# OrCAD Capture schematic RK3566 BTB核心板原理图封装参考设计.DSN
size A3; title: 野火_EBF RK3568 BTB 底板; rev: V1.0; note: BTB Connector; note: https://yehuosm.tmall.com
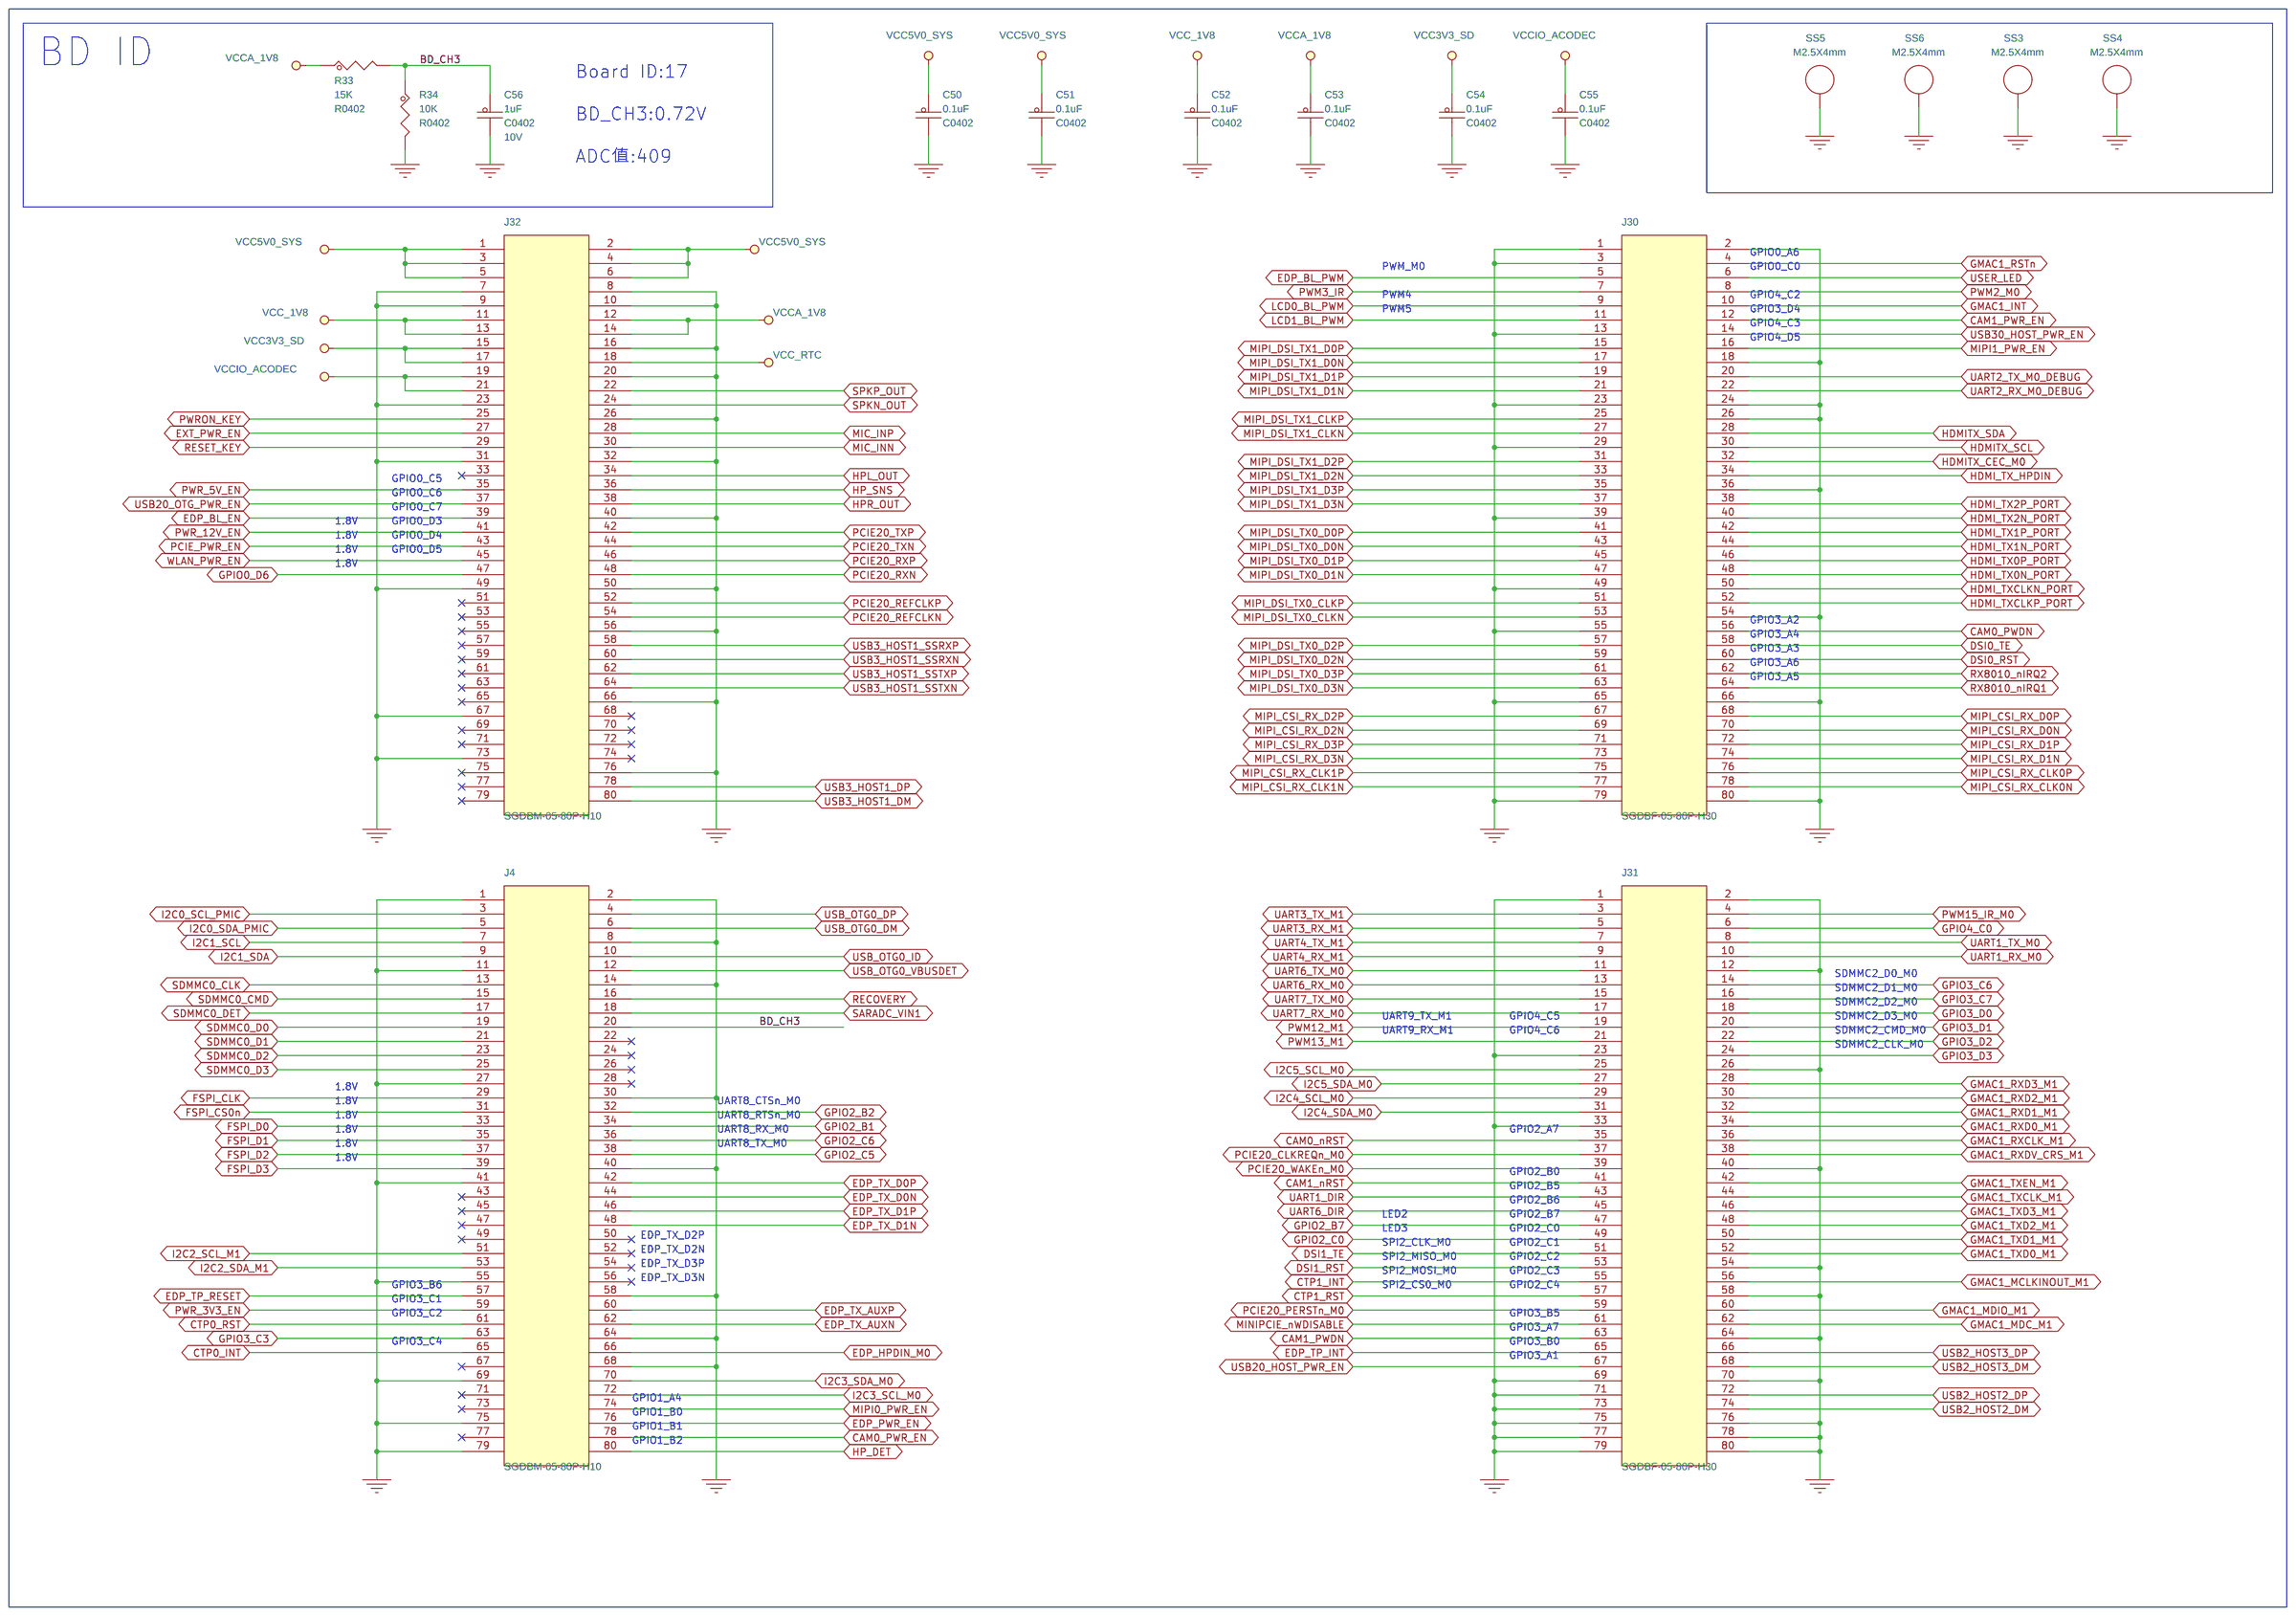
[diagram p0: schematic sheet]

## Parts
C50  0.1uF  [C0402]
C51  0.1uF  [C0402]
C52  0.1uF  [C0402]
C53  0.1uF  [C0402]
C54  0.1uF  [C0402]
C55  0.1uF  [C0402]
C56  1uF  [C0402]
J4  SGDBM-05-80P-H10  [SGDBM-05-80P-H10]
J30  SGDBF-05-80P-H30  [SGDBF-05-80P-H30]
J31  SGDBF-05-80P-H30  [SGDBF-05-80P-H30]
J32  SGDBM-05-80P-H10  [SGDBM-05-80P-H10]
R33  15K  [R0402]
R34  10K  [R0402]
SS3  M2.5X4mm  [SMTSO-M2r5]
SS4  M2.5X4mm  [SMTSO-M2r5]
SS5  M2.5X4mm  [SMTSO-M2r5]
SS6  M2.5X4mm  [SMTSO-M2r5]

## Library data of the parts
C50-C55 = CAP_NP: voltage: 50V; 规格: 贴片电容0.1uF 10% 50V X5R 0402; 规格编号: 0402X104K500NT; 规格书: 风华电容.pdf; 价格: 0.029826; 类别: 贴片电容0402; 品牌: 风华; 生命周期: 量产; 条码: EBF29060118
C56 = CAP_NP: Voltage: 10V; 规格: 贴片电容1uF 10% 10V X5R 0402; 规格编号: 0402X105K100NT; 规格书: 风华电容.pdf; 价格: 0.01191; 类别: 贴片电容0402; 品牌: 风华; 生命周期: 量产; 条码: EBF29060121
J4 J32 = SGDBM-05-80P-H10: 规格: 0.5mm BTB公座2*40P 双槽 立贴式 合高4.0mm; 规格书: 山谷道_双槽板对板公母立贴式0_5mm.pdf; 类别: BTB连接器; 品牌: 山谷道; 生命周期: 量产; 条码: EBFCIS221220164941
J30 J31 = SGDBM-05-80P-H10: 规格: 0.5mm BTB母座2*40P 双槽 立贴式 合高4.0mm; 规格书: 山谷道_双槽板对板公母立贴式0_5mm.pdf; 类别: BTB连接器; 品牌: 山谷道; 生命周期: 量产; 条码: EBFCIS221220165510
R33 = RES: 规格: 贴片电阻15K 1% 1/16W 0402; 规格编号: RI0402L1502FT; 规格书: 合科泰-RI系列电阻.pdf; 类别: 贴片电阻0402; 品牌: 合科泰; 生命周期: 量产; 条码: EBF29070222
R34 = RES: 规格: 贴片电阻10K 1% 1/16W 0402; 规格编号: 0402WGF1002TCE; 规格书: 厚声-无铅厚膜电阻.pdf; 价格: 0.002773; 类别: 贴片电阻0402; 品牌: 厚声; 生命周期: 量产; 条码: EBF29070046
SS3-SS6 = SPACER: 备注: BTB核心板固定铜柱; 规格: SMT贴片螺母M2.5 台阶高度1.4MM 台阶外径：4.5MM 螺柱长度：4MM; 规格编号: SMTSO2540CTJ; 规格书: 雄和远景_SMTSO2530CTJ.pdf; 类别: 贴片螺母; 品牌: 雄和远景; 生命周期: 量产; 条码: EBFCIS230525101139

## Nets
GND: C50.2 C51.2 C52.2 C53.2 C54.2 C55.2 C56.2 J4.1 J4.2 J4.8 J4.11 J4.14 J4.27 J4.30 J4.40 J4.41 J4.55 J4.58 J4.64 J4.68 J4.69 J4.75 J4.79 J30.1 J30.2 J30.3 J30.13 J30.18 J30.23 J30.24 J30.26 J30.29 J30.36 J30.39 J30.49 J30.54 J30.55 J30.65 J30.66 J30.79 J30.80 J31.1 J31.2 J31.12 J31.23 J31.26 J31.33 J31.40 J31.54 J31.58 J31.64 J31.69 J31.70 J31.71 J31.73 J31.75 J31.76 J31.77 J31.78 J31.79 J31.80 J32.7 J32.8 J32.9 J32.10 J32.16 J32.20 J32.23 J32.26 J32.31 J32.32 J32.40 J32.49 J32.50 J32.56 J32.66 J32.67 J32.73 J32.76 R34.2 SS3.1(NC) SS4.1(NC) SS5.1(NC) SS6.1(NC)
VCC3V3_SD: C54.1 J32.15 J32.17
VCC5V0_SYS: C50.1 C51.1 J32.1 J32.2 J32.3 J32.4 J32.5 J32.6
VCC_1V8: C52.1 J32.11 J32.13
VCC_RTC: J32.18
VCCA_1V8: C53.1 J32.12 J32.14 R33.1
VCCIO_ACODEC: C55.1 J32.19 J32.21
BD_CH3: C56.1 J4.20 R33.2 R34.1
CAM0_nRST: J31.35
CAM0_PWDN: J30.56
CAM0_PWR_EN: J4.78
CAM1_nRST: J31.41
CAM1_PWDN: J31.63
CAM1_PWR_EN: J30.12
CTP0_INT: J4.65
CTP0_RST: J4.61
CTP1_INT: J31.55
CTP1_RST: J31.57
DSI0_RST: J30.60
DSI0_TE: J30.58
DSI1_RST: J31.53
DSI1_TE: J31.51
EDP_BL_EN: J32.39
EDP_BL_PWM: J30.5
EDP_HPDIN_M0: J4.66
EDP_PWR_EN: J4.76
EDP_TP_INT: J31.65
EDP_TP_RESET: J4.57
EDP_TX_AUXN: J4.62
EDP_TX_AUXP: J4.60
EDP_TX_D0N: J4.44
EDP_TX_D0P: J4.42
EDP_TX_D1N: J4.48
EDP_TX_D1P: J4.46
EXT_PWR_EN: J32.27
FSPI_CLK: J4.29
FSPI_CS0n: J4.31
FSPI_D0: J4.33
FSPI_D1: J4.35
FSPI_D2: J4.37
FSPI_D3: J4.39
GMAC1_INT: J30.10
GMAC1_MCLKINOUT_M1: J31.56
GMAC1_MDC_M1: J31.62
GMAC1_MDIO_M1: J31.60
GMAC1_RSTn: J30.4
GMAC1_RXCLK_M1: J31.36
GMAC1_RXD0_M1: J31.34
GMAC1_RXD1_M1: J31.32
GMAC1_RXD2_M1: J31.30
GMAC1_RXD3_M1: J31.28
GMAC1_RXDV_CRS_M1: J31.38
GMAC1_TXCLK_M1: J31.44
GMAC1_TXD0_M1: J31.52
GMAC1_TXD1_M1: J31.50
GMAC1_TXD2_M1: J31.48
GMAC1_TXD3_M1: J31.46
GMAC1_TXEN_M1: J31.42
GPIO0_D6: J32.47
GPIO2_B1: J4.34
GPIO2_B2: J4.32
GPIO2_B7: J31.47
GPIO2_C0: J31.49
GPIO2_C5: J4.38
GPIO2_C6: J4.36
GPIO3_C3: J4.63
GPIO3_C6: J31.14
GPIO3_C7: J31.16
GPIO3_D0: J31.18
GPIO3_D1: J31.20
GPIO3_D2: J31.22
GPIO3_D3: J31.24
GPIO4_C0: J31.6
HDMI_TX0N_PORT: J30.48
HDMI_TX0P_PORT: J30.46
HDMI_TX1N_PORT: J30.44
HDMI_TX1P_PORT: J30.42
HDMI_TX2N_PORT: J30.40
HDMI_TX2P_PORT: J30.38
HDMI_TX_HPDIN: J30.34
HDMI_TXCLKN_PORT: J30.50
HDMI_TXCLKP_PORT: J30.52
HDMITX_CEC_M0: J30.32
HDMITX_SCL: J30.30
HDMITX_SDA: J30.28
HP_DET: J4.80
HP_SNS: J32.36
HPL_OUT: J32.34
HPR_OUT: J32.38
I2C0_SCL_PMIC: J4.3
I2C0_SDA_PMIC: J4.5
I2C1_SCL: J4.7
I2C1_SDA: J4.9
I2C2_SCL_M1: J4.51
I2C2_SDA_M1: J4.53
I2C3_SCL_M0: J4.72
I2C3_SDA_M0: J4.70
I2C4_SCL_M0: J31.29
I2C4_SDA_M0: J31.31
I2C5_SCL_M0: J31.25
I2C5_SDA_M0: J31.27
LCD0_BL_PWM: J30.9
LCD1_BL_PWM: J30.11
MIC_INN: J32.30
MIC_INP: J32.28
MINIPCIE_nWDISABLE: J31.61
MIPI0_PWR_EN: J4.74
MIPI1_PWR_EN: J30.16
MIPI_CSI_RX_CLK0N: J30.78
MIPI_CSI_RX_CLK0P: J30.76
MIPI_CSI_RX_CLK1N: J30.77
MIPI_CSI_RX_CLK1P: J30.75
MIPI_CSI_RX_D0N: J30.70
MIPI_CSI_RX_D0P: J30.68
MIPI_CSI_RX_D1N: J30.74
MIPI_CSI_RX_D1P: J30.72
MIPI_CSI_RX_D2N: J30.69
MIPI_CSI_RX_D2P: J30.67
MIPI_CSI_RX_D3N: J30.73
MIPI_CSI_RX_D3P: J30.71
MIPI_DSI_TX0_CLKN: J30.53
MIPI_DSI_TX0_CLKP: J30.51
MIPI_DSI_TX0_D0N: J30.43
MIPI_DSI_TX0_D0P: J30.41
MIPI_DSI_TX0_D1N: J30.47
MIPI_DSI_TX0_D1P: J30.45
MIPI_DSI_TX0_D2N: J30.59
MIPI_DSI_TX0_D2P: J30.57
MIPI_DSI_TX0_D3N: J30.63
MIPI_DSI_TX0_D3P: J30.61
MIPI_DSI_TX1_CLKN: J30.27
MIPI_DSI_TX1_CLKP: J30.25
MIPI_DSI_TX1_D0N: J30.17
MIPI_DSI_TX1_D0P: J30.15
MIPI_DSI_TX1_D1N: J30.21
MIPI_DSI_TX1_D1P: J30.19
MIPI_DSI_TX1_D2N: J30.33
MIPI_DSI_TX1_D2P: J30.31
MIPI_DSI_TX1_D3N: J30.37
MIPI_DSI_TX1_D3P: J30.35
PCIE20_CLKREQn_M0: J31.37
PCIE20_PERSTn_M0: J31.59
PCIE20_REFCLKN: J32.54
PCIE20_REFCLKP: J32.52
PCIE20_RXN: J32.48
PCIE20_RXP: J32.46
PCIE20_TXN: J32.44
PCIE20_TXP: J32.42
PCIE20_WAKEn_M0: J31.39
PCIE_PWR_EN: J32.43
PWM2_M0: J30.8
PWM3_IR: J30.7
PWM12_M1: J31.19
PWM13_M1: J31.21
PWM15_IR_M0: J31.4
PWR_3V3_EN: J4.59
PWR_5V_EN: J32.35
PWR_12V_EN: J32.41
PWRON_KEY: J32.25
RECOVERY: J4.16
RESET_KEY: J32.29
RX8010_nIRQ1: J30.64
RX8010_nIRQ2: J30.62
SARADC_VIN1: J4.18
SDMMC0_CLK: J4.13
SDMMC0_CMD: J4.15
SDMMC0_D0: J4.19
SDMMC0_D1: J4.21
SDMMC0_D2: J4.23
SDMMC0_D3: J4.25
SDMMC0_DET: J4.17
SPKN_OUT: J32.24
SPKP_OUT: J32.22
UART1_DIR: J31.43
UART1_RX_M0: J31.10
UART1_TX_M0: J31.8
UART2_RX_M0_DEBUG: J30.22
UART2_TX_M0_DEBUG: J30.20
UART3_RX_M1: J31.5
UART3_TX_M1: J31.3
UART4_RX_M1: J31.9
UART4_TX_M1: J31.7
UART6_DIR: J31.45
UART6_RX_M0: J31.13
UART6_TX_M0: J31.11
UART7_RX_M0: J31.17
UART7_TX_M0: J31.15
USB2_HOST2_DM: J31.74
USB2_HOST2_DP: J31.72
USB2_HOST3_DM: J31.68
USB2_HOST3_DP: J31.66
USB3_HOST1_DM: J32.80
USB3_HOST1_DP: J32.78
USB3_HOST1_SSRXN: J32.60
USB3_HOST1_SSRXP: J32.58
USB3_HOST1_SSTXN: J32.64
USB3_HOST1_SSTXP: J32.62
USB20_HOST_PWR_EN: J31.67
USB20_OTG_PWR_EN: J32.37
USB30_HOST_PWR_EN: J30.14
USB_OTG0_DM: J4.6
USB_OTG0_DP: J4.4
USB_OTG0_ID: J4.10
USB_OTG0_VBUSDET: J4.12
USER_LED: J30.6
WLAN_PWR_EN: J32.45

Not connected (* = marked no-connect by the designer): J4 22* 24* 26* 28* 43* 45* 47* 49* 50* 52* 54* 56* 67* 71* 73* 77*; J32 33* 51* 53* 55* 57* 59* 61* 63* 65* 68* 69* 70* 71* 72* 74* 75* 77* 79*

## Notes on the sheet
- BD ID
- Board ID:17
- BD_CH3:0.72V
- ADC值:409
- GPIO0_A6
- PWM_M0
- GPIO0_C0
- PWM4
- GPIO4_C2
- PWM5
- GPIO3_D4
- GPIO4_C3
- GPIO4_D5
- GPIO0_C5
- GPIO0_C6
- GPIO0_C7
- 1.8V
- 1.8V
- GPIO0_D3
- GPIO0_D4
- 1.8V
- GPIO0_D5
- 1.8V
- GPIO3_A2
- GPIO3_A4
- GPIO3_A3
- GPIO3_A6
- GPIO3_A5
- SDMMC2_D0_M0
- SDMMC2_D1_M0
- SDMMC2_D2_M0
- UART9_TX_M1
- GPIO4_C5
- SDMMC2_D3_M0
- UART9_RX_M1
- GPIO4_C6
- SDMMC2_CMD_M0
- SDMMC2_CLK_M0
- 1.8V
- 1.8V
- UART8_CTSn_M0
- 1.8V
- UART8_RTSn_M0
- 1.8V
- UART8_RX_M0
- GPIO2_A7
- 1.8V
- UART8_TX_M0
- 1.8V
- GPIO2_B0
- GPIO2_B5
- GPIO2_B6
- LED2
- GPIO2_B7
- EDP_TX_D2P
- LED3
- GPIO2_C0
- EDP_TX_D2N
- SPI2_CLK_M0
- GPIO2_C1
- EDP_TX_D3P
- SPI2_MISO_M0
- SPI2_MOSI_M0
- GPIO2_C2
- GPIO2_C3
- GPIO3_B6
- EDP_TX_D3N
- SPI2_CS0_M0
- GPIO2_C4
- GPIO3_C1
- GPIO3_C2
- GPIO3_B5
- GPIO3_A7
- GPIO3_C4
- GPIO3_B0
- GPIO3_A1
- GPIO1_A4
- GPIO1_B0
- GPIO1_B1
- GPIO1_B2
